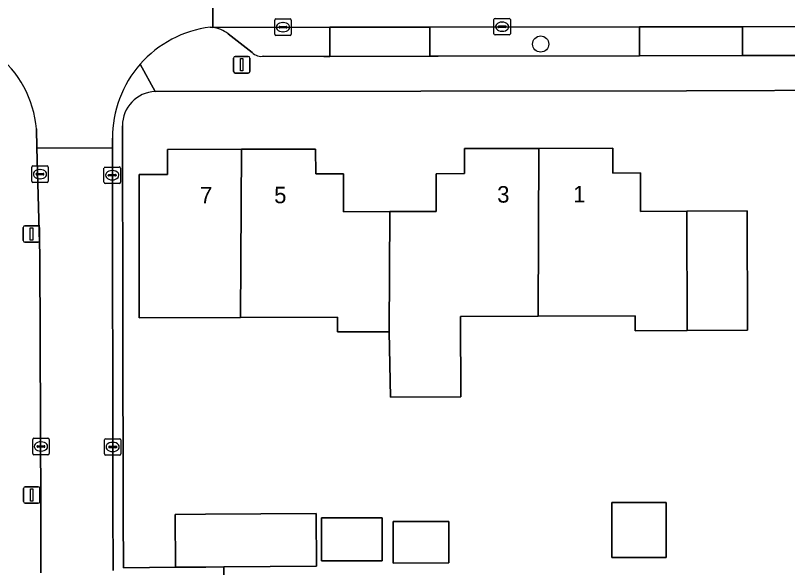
# Model space of a CAD drawing. Extents: x 160455 to 162082, y 388339 to 389736.
# Drawn here: x 160945.32 to 160992.11, y 388590.36 to 388623.81 of the extents above; entities that cross this region are included whole.
import ezdxf

# ---------------------------------------------------------------- set-up
doc = ezdxf.new("R2010")
doc.units = 0
for name, color, linetype in [('IMGEO_Boom', 7, 'Continuous'), ('IMGEO_Erf', 7, 'Continuous'), ('IMGEO_Kolk', 7, 'Continuous'), ('IMGEO_Lichtmast', 7, 'Continuous'), ('IMGEO_Muur', 7, 'Continuous'), ('IMGEO_Pand', 7, 'Continuous'), ('IMGEO_Pand_nummerreeks', 7, 'Continuous'), ('IMGEO_Parkeervlak_open', 7, 'Continuous'), ('IMGEO_Rijbaan_lokaal_open', 7, 'Continuous'), ('IMGEO_Voetpad_open', 7, 'Continuous')]:
    doc.layers.add(name, color=color, linetype=linetype)

msp = doc.modelspace()

# ---------------------------------------------------------------- linework, layer by layer
at = {"layer": 'IMGEO_Boom'}
msp.add_circle((160977.147, 388622.077), 0.489, dxfattribs=at)
at = {"layer": 'IMGEO_Erf'}
for points in [[(161000.909, 388608.334), (161000.892, 388615.187), (160996.682, 388615.177), (160996.672, 388619.278), (160985.977, 388619.25), (160953.788, 388619.195)], [(160951.807, 388617.13), (160951.827, 388605.484), (160951.847, 388593.555), (160951.861, 388590.348), (160955.023, 388590.37), (160955, 388593.578), (160956.836, 388593.591), (160963.536, 388593.64), (160963.56, 388590.431), (160957.949, 388590.391), (160958.051, 388555.395)]]:
    msp.add_lwpolyline(points, dxfattribs=at)
for points in [[(160989.687, 388604.736), (160986.017, 388604.721), (160982.878, 388604.708), (160982.875, 388605.608), (160977.005, 388605.584), (160972.296, 388605.564), (160972.312, 388600.698), (160968.052, 388600.684), (160967.971, 388604.647), (160964.841, 388604.634), (160964.838, 388605.534), (160958.958, 388605.51), (160952.827, 388605.484), (160952.815, 388614.175), (160954.535, 388614.18), (160954.531, 388615.691), (160959.011, 388615.704), (160963.511, 388615.717), (160963.515, 388614.206), (160965.195, 388614.211), (160965.202, 388611.912), (160968.012, 388611.921), (160970.822, 388611.929), (160970.816, 388614.223), (160972.54, 388614.229), (160972.535, 388615.74), (160977.035, 388615.756), (160981.515, 388615.772), (160981.52, 388614.261), (160983.201, 388614.267), (160983.203, 388611.938), (160985.996, 388611.95), (160989.656, 388611.965)], [(160984.758, 388590.961), (160981.47, 388590.961), (160981.47, 388594.305), (160984.758, 388594.305)], [(160967.547, 388590.772), (160963.874, 388590.766), (160963.87, 388593.369), (160967.542, 388593.375)], [(160971.581, 388593.148), (160971.585, 388590.633), (160968.219, 388590.628), (160968.214, 388593.142)]]:
    msp.add_lwpolyline(points, close=True, dxfattribs=at)
msp.add_arc((160953.865, 388617.138), 2.059, 92.1575, 180.2213, dxfattribs=at)
at = {"layer": 'IMGEO_Kolk'}
for p, q in [((160961.035, 388622.673), (160961.035, 388623.525)), ((160961.11, 388623.599), (160961.962, 388623.599)), ((160962.036, 388623.525), (160962.036, 388622.673)), ((160974.311, 388622.704), (160974.311, 388623.556)), ((160974.386, 388623.63), (160975.238, 388623.63)), ((160975.312, 388623.556), (160975.312, 388622.704)), ((160961.294, 388623.093), (160961.294, 388623.105)), ((160961.732, 388623.056), (160961.334, 388623.056)), ((160961.337, 388623.142), (160961.735, 388623.142)), ((160961.523, 388623.379), (160961.548, 388623.379)), ((160961.778, 388623.105), (160961.778, 388623.093)), ((160974.57, 388623.124), (160974.57, 388623.136)), ((160975.008, 388623.087), (160974.61, 388623.087)), ((160974.613, 388623.173), (160975.011, 388623.173)), ((160974.799, 388623.41), (160974.824, 388623.41)), ((160975.054, 388623.136), (160975.054, 388623.124)), ((160961.962, 388622.599), (160961.11, 388622.599)), ((160961.546, 388622.819), (160961.521, 388622.819)), ((160975.238, 388622.63), (160974.386, 388622.63)), ((160974.822, 388622.85), (160974.797, 388622.85)), ((160946.308, 388613.769), (160946.308, 388614.621)), ((160946.383, 388614.695), (160947.235, 388614.695)), ((160947.309, 388614.621), (160947.309, 388613.769)), ((160950.763, 388614.627), (160951.615, 388614.627)), ((160946.567, 388614.189), (160946.567, 388614.201)), ((160947.005, 388614.152), (160946.607, 388614.152)), ((160946.61, 388614.238), (160947.008, 388614.238)), ((160946.796, 388614.475), (160946.821, 388614.475)), ((160947.051, 388614.201), (160947.051, 388614.189)), ((160950.688, 388613.701), (160950.688, 388614.553)), ((160950.947, 388614.121), (160950.947, 388614.133)), ((160950.99, 388614.17), (160951.388, 388614.17)), ((160951.176, 388614.407), (160951.201, 388614.407)), ((160951.431, 388614.133), (160951.431, 388614.121)), ((160951.689, 388614.553), (160951.689, 388613.701)), ((160947.235, 388613.695), (160946.383, 388613.695)), ((160946.819, 388613.915), (160946.794, 388613.915)), ((160951.385, 388614.084), (160950.987, 388614.084)), ((160951.199, 388613.847), (160951.174, 388613.847)), ((160951.615, 388613.627), (160950.763, 388613.627)), ((160946.366, 388597.268), (160946.366, 388598.12)), ((160946.441, 388598.194), (160947.293, 388598.194)), ((160946.854, 388597.974), (160946.879, 388597.974)), ((160947.367, 388598.12), (160947.367, 388597.268)), ((160950.715, 388597.237), (160950.715, 388598.089)), ((160950.79, 388598.163), (160951.642, 388598.163)), ((160951.203, 388597.943), (160951.228, 388597.943)), ((160951.716, 388598.089), (160951.716, 388597.237)), ((160946.625, 388597.688), (160946.625, 388597.7)), ((160947.063, 388597.651), (160946.665, 388597.651)), ((160946.668, 388597.737), (160947.066, 388597.737)), ((160946.877, 388597.414), (160946.852, 388597.414)), ((160947.109, 388597.7), (160947.109, 388597.688)), ((160950.974, 388597.657), (160950.974, 388597.669)), ((160951.412, 388597.62), (160951.014, 388597.62)), ((160951.017, 388597.706), (160951.415, 388597.706)), ((160951.226, 388597.383), (160951.201, 388597.383)), ((160951.458, 388597.669), (160951.458, 388597.657)), ((160947.293, 388597.194), (160946.441, 388597.194)), ((160951.642, 388597.163), (160950.79, 388597.163))]:
    msp.add_line(p, q, dxfattribs=at)
for points in [[(160961.035, 388622.673), (160961.035, 388623.525)], [(160961.11, 388623.599), (160961.962, 388623.599)], [(160962.036, 388623.525), (160962.036, 388622.673)], [(160974.311, 388622.704), (160974.311, 388623.556)], [(160974.386, 388623.63), (160975.238, 388623.63)], [(160975.312, 388623.556), (160975.312, 388622.704)], [(160961.962, 388622.599), (160961.11, 388622.599)], [(160975.238, 388622.63), (160974.386, 388622.63)], [(160946.308, 388613.769), (160946.308, 388614.621)], [(160946.383, 388614.695), (160947.235, 388614.695)], [(160947.309, 388614.621), (160947.309, 388613.769)], [(160950.763, 388614.627), (160951.615, 388614.627)], [(160950.688, 388613.701), (160950.688, 388614.553)], [(160951.689, 388614.553), (160951.689, 388613.701)], [(160947.235, 388613.695), (160946.383, 388613.695)], [(160951.615, 388613.627), (160950.763, 388613.627)], [(160946.366, 388597.268), (160946.366, 388598.12)], [(160946.441, 388598.194), (160947.293, 388598.194)], [(160947.367, 388598.12), (160947.367, 388597.268)], [(160950.715, 388597.237), (160950.715, 388598.089)], [(160950.79, 388598.163), (160951.642, 388598.163)], [(160951.716, 388598.089), (160951.716, 388597.237)], [(160947.293, 388597.194), (160946.441, 388597.194)], [(160951.642, 388597.163), (160950.79, 388597.163)]]:
    msp.add_lwpolyline(points, dxfattribs=at)
for centre, radius, start, end in [((160961.112, 388623.523), 0.0765, 91.552, 178.448), ((160961.112, 388623.523), 0.0765, 91.552, 178.448), ((160961.96, 388623.523), 0.0765, 1.552, 88.448), ((160961.96, 388623.523), 0.0765, 1.552, 88.448), ((160974.388, 388623.554), 0.0765, 91.552, 178.448), ((160974.388, 388623.554), 0.0765, 91.552, 178.448), ((160975.236, 388623.554), 0.0765, 1.552, 88.448), ((160975.236, 388623.554), 0.0765, 1.552, 88.448), ((160961.334, 388623.102), 0.0403, 85.8775, 175.7526), ((160961.331, 388623.092), 0.0366, 178.938, 274.7102), ((160961.735, 388623.099), 0.043, 264.8664, 352.4533), ((160961.739, 388623.104), 0.0386, 1.7309, 96.639), ((160974.61, 388623.133), 0.0403, 85.8775, 175.7526), ((160974.607, 388623.123), 0.0366, 178.938, 274.7102), ((160975.011, 388623.13), 0.043, 264.8664, 352.4533), ((160975.015, 388623.135), 0.0386, 1.7309, 96.639), ((160961.112, 388622.675), 0.0765, 181.552, 268.448), ((160961.112, 388622.675), 0.0765, 181.552, 268.448), ((160961.96, 388622.675), 0.0765, 271.552, 358.448), ((160961.96, 388622.675), 0.0765, 271.552, 358.448), ((160974.388, 388622.706), 0.0765, 181.552, 268.448), ((160974.388, 388622.706), 0.0765, 181.552, 268.448), ((160975.236, 388622.706), 0.0765, 271.552, 358.448), ((160975.236, 388622.706), 0.0765, 271.552, 358.448), ((160946.385, 388614.619), 0.0765, 91.552, 178.448), ((160946.385, 388614.619), 0.0765, 91.552, 178.448), ((160947.233, 388614.619), 0.0765, 1.552, 88.448), ((160947.233, 388614.619), 0.0765, 1.552, 88.448), ((160950.765, 388614.551), 0.0765, 91.552, 178.448), ((160950.765, 388614.551), 0.0765, 91.552, 178.448), ((160951.613, 388614.551), 0.0765, 1.552, 88.448), ((160951.613, 388614.551), 0.0765, 1.552, 88.448), ((160946.607, 388614.198), 0.0403, 85.8775, 175.7526), ((160946.604, 388614.188), 0.0366, 178.938, 274.7102), ((160947.008, 388614.195), 0.043, 264.8664, 352.4533), ((160947.012, 388614.2), 0.0386, 1.7309, 96.639), ((160950.987, 388614.13), 0.0403, 85.8775, 175.7526), ((160951.392, 388614.132), 0.0386, 1.7309, 96.639), ((160946.385, 388613.771), 0.0765, 181.552, 268.448), ((160946.385, 388613.771), 0.0765, 181.552, 268.448), ((160947.233, 388613.771), 0.0765, 271.552, 358.448), ((160947.233, 388613.771), 0.0765, 271.552, 358.448), ((160950.765, 388613.703), 0.0765, 181.552, 268.448), ((160950.765, 388613.703), 0.0765, 181.552, 268.448), ((160950.984, 388614.12), 0.0366, 178.938, 274.7102), ((160951.388, 388614.127), 0.043, 264.8664, 352.4533), ((160951.613, 388613.703), 0.0765, 271.552, 358.448), ((160951.613, 388613.703), 0.0765, 271.552, 358.448), ((160946.443, 388598.118), 0.0765, 91.552, 178.448), ((160946.443, 388598.118), 0.0765, 91.552, 178.448), ((160947.291, 388598.118), 0.0765, 1.552, 88.448), ((160947.291, 388598.118), 0.0765, 1.552, 88.448), ((160950.792, 388598.087), 0.0765, 91.552, 178.448), ((160950.792, 388598.087), 0.0765, 91.552, 178.448), ((160951.64, 388598.087), 0.0765, 1.552, 88.448), ((160951.64, 388598.087), 0.0765, 1.552, 88.448), ((160946.665, 388597.697), 0.0403, 85.8775, 175.7526), ((160946.662, 388597.687), 0.0366, 178.938, 274.7102), ((160947.066, 388597.694), 0.043, 264.8664, 352.4533), ((160947.07, 388597.699), 0.0386, 1.7309, 96.639), ((160951.014, 388597.666), 0.0403, 85.8775, 175.7526), ((160951.011, 388597.656), 0.0366, 178.938, 274.7102), ((160951.415, 388597.663), 0.043, 264.8664, 352.4533), ((160951.419, 388597.668), 0.0386, 1.7309, 96.639), ((160946.443, 388597.27), 0.0765, 181.552, 268.448), ((160946.443, 388597.27), 0.0765, 181.552, 268.448), ((160947.291, 388597.27), 0.0765, 271.552, 358.448), ((160947.291, 388597.27), 0.0765, 271.552, 358.448), ((160950.792, 388597.239), 0.0765, 181.552, 268.448), ((160950.792, 388597.239), 0.0765, 181.552, 268.448), ((160951.64, 388597.239), 0.0765, 271.552, 358.448), ((160951.64, 388597.239), 0.0765, 271.552, 358.448)]:
    msp.add_arc(centre, radius, start, end, dxfattribs=at)
for centre, major_axis, ratio, start_param, end_param in [((160961.522, 388623.099), (-0.387, 0.002), 0.722429, 4.712389, 7.853982), ((160961.547, 388623.099), (-0.39, 0.002), 0.717154, 1.570796, 4.712389), ((160974.798, 388623.13), (-0.387, 0.002), 0.722429, 4.712389, 7.853982), ((160974.823, 388623.13), (-0.39, 0.002), 0.717154, 1.570796, 4.712389), ((160946.795, 388614.195), (-0.387, 0.002), 0.722429, 4.712389, 7.853982), ((160946.82, 388614.195), (-0.39, 0.002), 0.717154, 1.570796, 4.712389), ((160951.175, 388614.127), (-0.387, 0.002), 0.722429, 4.712389, 7.853982), ((160951.2, 388614.127), (-0.39, 0.002), 0.717154, 1.570796, 4.712389), ((160946.853, 388597.694), (-0.387, 0.002), 0.722429, 4.712389, 7.853982), ((160946.878, 388597.694), (-0.39, 0.002), 0.717154, 1.570796, 4.712389), ((160951.202, 388597.663), (-0.387, 0.002), 0.722429, 4.712389, 7.853982), ((160951.227, 388597.663), (-0.39, 0.002), 0.717154, 1.570796, 4.712389)]:
    msp.add_ellipse(centre, major_axis=major_axis, ratio=ratio, start_param=start_param, end_param=end_param, dxfattribs=at)
at = {"layer": 'IMGEO_Lichtmast'}
for p, q in [((160958.54, 388620.423), (160958.54, 388621.223)), ((160958.54, 388621.223), (160958.54, 388620.423)), ((160958.64, 388621.323), (160959.43, 388621.323)), ((160959.43, 388621.323), (160958.64, 388621.323)), ((160959.53, 388621.223), (160959.53, 388620.423)), ((160959.53, 388620.423), (160959.53, 388621.223)), ((160959.43, 388620.323), (160958.64, 388620.323)), ((160958.64, 388620.323), (160959.43, 388620.323)), ((160945.799, 388610.168), (160945.799, 388610.968)), ((160945.799, 388610.968), (160945.799, 388610.168)), ((160945.899, 388611.068), (160946.689, 388611.068)), ((160946.689, 388611.068), (160945.899, 388611.068)), ((160946.789, 388610.968), (160946.789, 388610.168)), ((160946.789, 388610.168), (160946.789, 388610.968)), ((160946.689, 388610.068), (160945.899, 388610.068)), ((160945.899, 388610.068), (160946.689, 388610.068)), ((160945.815, 388594.35), (160945.815, 388595.15)), ((160945.815, 388595.15), (160945.815, 388594.35)), ((160945.915, 388595.25), (160946.705, 388595.25)), ((160946.705, 388595.25), (160945.915, 388595.25)), ((160946.805, 388595.15), (160946.805, 388594.35)), ((160946.805, 388594.35), (160946.805, 388595.15)), ((160946.705, 388594.25), (160945.915, 388594.25)), ((160945.915, 388594.25), (160946.705, 388594.25))]:
    msp.add_line(p, q, dxfattribs=at)
for points in [[(160958.96, 388621.198), (160959.11, 388621.198), (160959.11, 388620.448), (160958.96, 388620.448), (160958.96, 388621.198)], [(160946.219, 388610.943), (160946.369, 388610.943), (160946.369, 388610.193), (160946.219, 388610.193), (160946.219, 388610.943)], [(160946.235, 388595.125), (160946.385, 388595.125), (160946.385, 388594.375), (160946.235, 388594.375), (160946.235, 388595.125)]]:
    msp.add_lwpolyline(points, dxfattribs=at)
for centre, start, end in [((160958.64, 388621.223), 90, 180), ((160958.64, 388621.223), 90, 180), ((160959.43, 388621.223), 0, 90), ((160959.43, 388621.223), 360, 90), ((160958.64, 388620.423), 180, 270), ((160958.64, 388620.423), 180, 270), ((160959.43, 388620.423), 270, 0), ((160959.43, 388620.423), 270, 0), ((160945.899, 388610.968), 90, 180), ((160945.899, 388610.968), 90, 180), ((160946.689, 388610.968), 0, 90), ((160946.689, 388610.968), 360, 90), ((160945.899, 388610.168), 180, 270), ((160945.899, 388610.168), 180, 270), ((160946.689, 388610.168), 270, 0), ((160946.689, 388610.168), 270, 0), ((160945.915, 388595.15), 90, 180), ((160945.915, 388595.15), 90, 180), ((160946.705, 388595.15), 0, 90), ((160946.705, 388595.15), 360, 90), ((160945.915, 388594.35), 180, 270), ((160945.915, 388594.35), 180, 270), ((160946.705, 388594.35), 270, 0), ((160946.705, 388594.35), 270, 0)]:
    msp.add_arc(centre, 0.1, start, end, dxfattribs=at)
at = {"layer": 'IMGEO_Muur'}
for points in [[(160996.672, 388619.278), (160985.977, 388619.25)], [(160951.827, 388605.484), (160951.847, 388593.555)]]:
    msp.add_lwpolyline(points, dxfattribs=at)
at = {"layer": 'IMGEO_Pand'}
for points in [[(160959.011, 388615.704), (160954.531, 388615.691), (160954.535, 388614.18), (160952.815, 388614.175), (160952.827, 388605.484), (160958.958, 388605.51)], [(160959.011, 388615.704), (160958.958, 388605.51), (160964.838, 388605.534), (160964.841, 388604.634), (160967.971, 388604.647), (160968.012, 388611.921), (160965.202, 388611.912), (160965.195, 388614.211), (160963.515, 388614.206), (160963.511, 388615.717)], [(160977.035, 388615.756), (160972.535, 388615.74), (160972.54, 388614.229), (160970.816, 388614.223), (160970.822, 388611.929), (160968.012, 388611.921), (160967.971, 388604.647), (160968.052, 388600.684), (160972.312, 388600.698), (160972.296, 388605.564), (160977.005, 388605.584)], [(160985.996, 388611.95), (160983.203, 388611.938), (160983.201, 388614.267), (160981.52, 388614.261), (160981.515, 388615.772), (160977.035, 388615.756), (160977.005, 388605.584), (160982.875, 388605.608), (160982.878, 388604.708), (160986.017, 388604.721)], [(160985.996, 388611.95), (160986.017, 388604.721), (160989.687, 388604.736), (160989.656, 388611.965)], [(160984.758, 388590.961), (160984.758, 388594.305), (160981.47, 388594.305), (160981.47, 388590.961)], [(160955.023, 388590.37), (160956.859, 388590.383), (160957.949, 388590.391), (160963.56, 388590.431), (160963.536, 388593.64), (160956.836, 388593.591), (160955, 388593.578)], [(160967.547, 388590.772), (160967.542, 388593.375), (160963.87, 388593.369), (160963.874, 388590.766)], [(160968.214, 388593.142), (160968.219, 388590.628), (160971.585, 388590.633), (160971.581, 388593.148)]]:
    msp.add_lwpolyline(points, close=True, dxfattribs=at)
at = {"layer": 'IMGEO_Parkeervlak_open'}
for points in [[(160964.363, 388623.096), (160957.285, 388623.088)], [(160960.381, 388621.348), (160964.013, 388621.327), (160964.364, 388621.328), (160964.363, 388623.096)], [(161010.022, 388623.066), (161000, 388623.134), (160989.379, 388623.123), (160989.381, 388621.38), (160989.977, 388621.381), (161000, 388621.379), (161007.575, 388621.378)], [(160958.206, 388622.705), (160959.657, 388621.562)]]:
    msp.add_lwpolyline(points, dxfattribs=at)
for points in [[(160970.439, 388623.102), (160964.363, 388623.096), (160964.364, 388621.328), (160970.441, 388621.34)], [(160983.144, 388623.116), (160970.439, 388623.102), (160970.441, 388621.34), (160970.945, 388621.341), (160983.146, 388621.367)], [(160989.379, 388623.123), (160983.144, 388623.116), (160983.146, 388621.367), (160989.381, 388621.38)]]:
    msp.add_lwpolyline(points, close=True, dxfattribs=at)
for centre, radius, start, end in [((160957.065, 388621.259), 1.842, 51.7094, 83.1304), ((160960.218, 388622.129), 0.798, 225.3037, 281.763)]:
    msp.add_arc(centre, radius, start, end, dxfattribs=at)
at = {"layer": 'IMGEO_Rijbaan_lokaal_open'}
msp.add_lwpolyline([(161010.049, 388627.741), (161000, 388627.698), (160988.98, 388627.682), (160982.007, 388627.672), (160969.838, 388627.654), (160963.828, 388627.645), (160957.279, 388627.635), (160957.285, 388623.088), (160964.363, 388623.096), (160970.439, 388623.102), (160983.144, 388623.116), (160989.379, 388623.123), (161000, 388623.134), (161010.022, 388623.066)], close=True, dxfattribs=at)
for points in [[(160957.122, 388623.1), (160957.285, 388623.088), (160957.279, 388627.635), (160956.983, 388627.6), (160941.339, 388627.57), (160941.315, 388623.065), (160941.313, 388622.774)], [(160946.592, 388616.937), (160946.624, 388615.788), (160951.194, 388615.777), (160951.193, 388616.365)], [(160951.224, 388593.835), (160951.194, 388615.777), (160946.624, 388615.788), (160946.807, 388609.308), (160946.861, 388593.811), (160946.863, 388590.044)], [(160951.241, 388590.183), (160951.242, 388590.402), (160951.224, 388593.835)]]:
    msp.add_lwpolyline(points, dxfattribs=at)
for centre, radius, start, end in [((160957.966, 388616.378), 6.775, 97.1545, 138.6252), ((160940.092, 388616.381), 6.524, 4.885, 51.7793), ((160957.96, 388616.383), 6.767, 138.6246, 180.1543)]:
    msp.add_arc(centre, radius, start, end, dxfattribs=at)
at = {"layer": 'IMGEO_Voetpad_open'}
for points in [[(160957.285, 388623.088), (160957.122, 388623.1)], [(160959.657, 388621.562), (160958.206, 388622.705)], [(160952.882, 388620.856), (160953.788, 388619.195), (160985.977, 388619.25), (160996.672, 388619.278), (161001.88, 388619.273), (161013.083, 388619.262), (161014.862, 388621.424)], [(161007.575, 388621.378), (161000, 388621.379), (160989.977, 388621.381), (160989.381, 388621.38), (160983.146, 388621.367), (160970.945, 388621.341), (160970.441, 388621.34), (160964.364, 388621.328), (160964.013, 388621.327), (160960.381, 388621.348)], [(160953.788, 388619.195), (160952.882, 388620.856)], [(160946.863, 388590.044), (160946.861, 388593.811), (160946.807, 388609.308), (160946.624, 388615.788), (160946.592, 388616.937)], [(160958.183, 388500), (160958.111, 388537.937), (160958.098, 388540.667), (160958.068, 388552.684), (160958.051, 388555.395), (160957.949, 388590.391), (160956.859, 388590.383), (160955.023, 388590.37), (160951.861, 388590.348), (160951.847, 388593.555), (160951.827, 388605.484), (160951.807, 388617.13)], [(160951.193, 388616.365), (160951.194, 388615.777), (160951.224, 388593.835), (160951.242, 388590.402), (160951.241, 388590.183)]]:
    msp.add_lwpolyline(points, dxfattribs=at)
for centre, radius, start, end in [((160957.966, 388616.378), 6.775, 97.1545, 138.6252), ((160957.065, 388621.259), 1.842, 51.7094, 83.1304), ((160940.092, 388616.381), 6.524, 4.885, 51.7793), ((160960.218, 388622.129), 0.798, 225.3037, 281.763), ((160957.96, 388616.383), 6.767, 138.6246, 180.1543), ((160953.865, 388617.138), 2.059, 92.1575, 180.2213)]:
    msp.add_arc(centre, radius, start, end, dxfattribs=at)

# ---------------------------------------------------------------- texts
at = {"layer": 'IMGEO_Pand_nummerreeks'}
for s, rotation, p in [('7', 0.1659, (160956.51, 388612.417)), ('5', 0.1659, (160961, 388612.43)), ('3', 0.2042, (160974.516, 388612.467)), ('1', 0.2042, (160979.12, 388612.484))]:
    msp.add_text(s, height=1, rotation=rotation, dxfattribs=at).set_placement(p)

doc.saveas('drawing.dxf')
